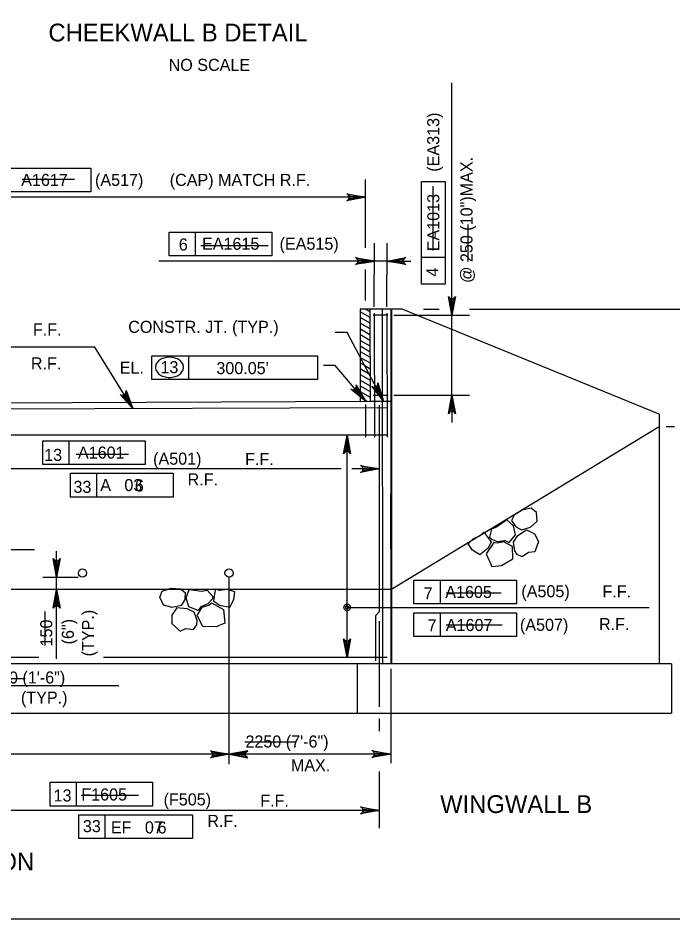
# Model space of a CAD drawing. Extents: x 179 to 454, y -271 to 54.
# Drawn here: x 258.44 to 264.96, y -43.25 to -34.28 of the extents above; entities that cross this region are included whole.
import ezdxf

# ---------------------------------------------------------------- set-up
doc = ezdxf.new("R2010")
doc.units = 0
for name, color, linetype in [('Level 1', 7, 'Continuous'), ('Level 10', 7, 'Continuous'), ('Level 3', 7, 'Continuous'), ('Level 4', 7, 'Continuous'), ('Level 41', 7, 'Continuous'), ('Level 5', 7, 'Continuous')]:
    doc.layers.add(name, color=color, linetype=linetype)

# ---------------------------------------------------------------- blocks, each defined once
blk = doc.blocks.new('ROCK')
at = {"layer": 'Level 4'}
for points in [[(1.578, 0.725), (1.471, 0.551), (1.586, 0.338), (1.78, 0.206), (2.086, 0.269), (2.323, 0.452), (2.328, 0.749), (2.171, 0.911), (1.856, 0.872)], [(0.734, -0.018), (0.934, -0.106), (1.192, -0.099), (1.321, -0.177), (1.562, 0.063), (1.519, 0.367), (1.313, 0.589), (0.948, 0.369), (0.769, 0.319), (0.674, 0.055)], [(0.498, 0.24), (0.588, 0.107), (0.715, -0.096), (0.595, -0.305), (0.299, -0.506), (0.067, -0.329), (-0.063, -0.098), (0.135, 0.068), (0.386, 0.147)], [(1.488, -0.478), (1.468, -0.178), (1.636, 0.025), (1.939, 0.193), (2.2, 0.032), (2.312, -0.229), (2.154, -0.57), (1.947, -0.574), (1.718, -0.703), (1.56, -0.603)], [(0.806, -0.129), (0.519, -0.492), (0.672, -0.928), (0.991, -0.931), (1.399, -0.738), (1.422, -0.324), (1.149, -0.136), (0.916, -0.16)]]:
    blk.add_lwpolyline(points, close=True, dxfattribs=at)

msp = doc.modelspace()

# ---------------------------------------------------------------- linework, layer by layer
at = {"layer": 'Level 1'}
msp.add_lwpolyline([(245.497, -43.25), (276.997, -43.25), (276.997, -22.75), (245.497, -22.75)], close=True, dxfattribs=at)
at = {"layer": 'Level 10'}
for p, q in [((261.8423, -37.2006), (261.9415, -37.2578)), ((261.8442, -37.177), (261.8467, -38.0953)), ((262.1497, -37.177), (261.8442, -37.177)), ((261.8998, -37.177), (261.9412, -37.2009)), ((261.9431, -37.177), (261.9457, -38.0948)), ((262.0661, -37.177), (262.0687, -40.708)), ((262.1497, -37.177), (262.1497, -40.708)), ((262.1587, -37.177), (262.1587, -40.708)), ((262.2652, -37.177), (262.1587, -37.177)), ((264.8223, -38.2227), (262.2652, -37.177)), ((261.8426, -37.2576), (261.9418, -37.3148)), ((261.8428, -37.3146), (261.9421, -37.3718)), ((261.8432, -37.3716), (261.9423, -37.4288)), ((261.8434, -37.4286), (261.9426, -37.4858)), ((261.8438, -37.4856), (261.9429, -37.5428)), ((261.844, -37.5426), (261.9432, -37.5998)), ((261.8443, -37.5995), (261.9435, -37.6568)), ((261.8446, -37.6565), (261.8471, -37.6579)), ((261.8471, -37.6579), (261.9437, -37.7138)), ((261.8448, -37.7135), (261.8907, -37.74)), ((261.8907, -37.74), (261.9441, -37.7707)), ((261.8452, -37.7705), (261.9345, -37.8221)), ((261.8454, -37.8275), (261.9446, -37.8847)), ((261.9345, -37.8221), (261.9443, -37.8278)), ((261.8458, -37.8845), (261.9449, -37.9417)), ((261.846, -37.9415), (261.9452, -37.9988)), ((261.8463, -37.9985), (261.9455, -38.0557)), ((253.2639, -38.1317), (261.9457, -38.0948)), ((261.8466, -38.0555), (261.915, -38.0949)), ((261.9457, -38.0948), (262.1543, -38.0939)), ((264.8223, -38.2227), (264.8223, -40.708)), ((262.1497, -39.9698), (264.8223, -38.3458)), ((262.0111, -39.9698), (253.6367, -39.9698)), ((262.1543, -39.9698), (262.0111, -39.9698)), ((259.0207, -40.708), (256.7722, -40.708)), ((264.9454, -40.708), (259.0207, -40.708)), ((261.815, -40.708), (261.815, -41.2001)), ((264.9454, -40.708), (264.9454, -41.2001)), ((249.6966, -41.2001), (264.9454, -41.2001))]:
    msp.add_line(p, q, dxfattribs=at)
at = {"layer": 'Level 3'}
for p, q in [((262.7585, -37.2385), (262.7585, -34.9256)), ((258.1427, -35.774), (259.1642, -35.774)), ((259.1642, -35.774), (259.1642, -36.0102)), ((261.8995, -36.5671), (261.8995, -35.887)), ((262.4572, -36.9288), (262.4572, -35.9073)), ((262.4572, -35.9073), (262.6934, -35.9073)), ((262.6934, -35.9073), (262.6934, -36.9288)), ((259.1642, -36.0102), (258.1427, -36.0102)), ((261.8995, -36.0642), (257.699, -36.0642)), ((259.9434, -36.4099), (260.9649, -36.4099)), ((259.9434, -36.6461), (259.9434, -36.4099)), ((260.2072, -36.6461), (260.2072, -36.4099)), ((260.9649, -36.4099), (260.9649, -36.6461)), ((261.9841, -37.1565), (261.9867, -36.5225)), ((262.1107, -37.1565), (262.1133, -36.5225)), ((260.9649, -36.6461), (259.9434, -36.6461)), ((262.6934, -36.6652), (262.4572, -36.6652)), ((261.0277, -36.6997), (259.8401, -36.6997)), ((261.9859, -36.6997), (260.7614, -36.6997)), ((262.1133, -36.6997), (261.9867, -36.6997)), ((262.1126, -36.6997), (262.3496, -36.6997)), ((261.8995, -37.0904), (261.8995, -36.7846)), ((262.6934, -36.9288), (262.4572, -36.9288)), ((262.7585, -37.1204), (262.7585, -37.0023)), ((262.4756, -37.177), (262.633, -37.177)), ((262.9346, -37.177), (268.2215, -37.177)), ((262.1805, -37.2385), (262.9357, -37.2385)), ((262.7585, -38.0704), (262.7585, -37.2385)), ((261.7145, -37.4091), (261.5964, -37.4091)), ((262.0794, -38.0942), (261.7145, -37.4091)), ((259.2046, -37.5568), (256.5932, -37.5568)), ((259.5829, -38.1663), (259.2046, -37.5568)), ((259.7718, -37.6433), (260.1387, -37.6433)), ((259.7718, -37.8795), (259.7718, -37.6433)), ((260.1387, -37.8795), (260.1387, -37.6433)), ((260.1387, -37.6433), (261.4202, -37.6433)), ((261.4202, -37.6433), (261.4202, -37.8795)), ((261.5978, -37.7378), (261.4797, -37.7378)), ((261.8999, -38.095), (261.5978, -37.7378)), ((261.4202, -37.8795), (259.7718, -37.8795)), ((262.1805, -38.0332), (262.9357, -38.0332)), ((262.7585, -38.0704), (262.7585, -38.3066)), ((261.7154, -39.5806), (261.7154, -38.4319)), ((258.6842, -38.4892), (259.7057, -38.4892)), ((258.6842, -38.7255), (258.6842, -38.4892)), ((258.9479, -38.7255), (258.9479, -38.4892)), ((259.7057, -38.4892), (259.7057, -38.7255)), ((259.7057, -38.7255), (258.6842, -38.7255)), ((261.6557, -38.7692), (257.6659, -38.7692)), ((258.9612, -39.0487), (258.9612, -38.8125)), ((258.9612, -38.8125), (259.9827, -38.8125)), ((259.2249, -39.0487), (259.2249, -38.8125)), ((259.9827, -38.8125), (259.9827, -39.0487)), ((262.0361, -38.7692), (261.7622, -38.7692)), ((262.1497, -39.5671), (262.1497, -39.0198)), ((259.9827, -39.0487), (258.9612, -39.0487)), ((261.7154, -40.6465), (261.7154, -39.5068)), ((257.9022, -39.5727), (258.6038, -39.5727)), ((258.8218, -40.6597), (258.8218, -39.5877)), ((258.6867, -39.8468), (259.0362, -39.8468)), ((262.3814, -39.8768), (263.4029, -39.8768)), ((262.3814, -40.1131), (262.3814, -39.8768)), ((262.6451, -40.1131), (262.6451, -39.8768)), ((263.4029, -39.8768), (263.4029, -40.1131)), ((261.7154, -40.1481), (264.7239, -40.1481)), ((263.4029, -40.1131), (262.3814, -40.1131)), ((262.3814, -40.4363), (262.3814, -40.2001)), ((262.3814, -40.2001), (263.4029, -40.2001)), ((262.6451, -40.4363), (262.6451, -40.2001)), ((263.4029, -40.2001), (263.4029, -40.4363)), ((263.4029, -40.4363), (262.3814, -40.4363)), ((262.1498, -40.7605), (262.1498, -41.6998)), ((259.4417, -40.9298), (257.6044, -40.9298)), ((262.0361, -41.2551), (262.0361, -41.3808)), ((262.1498, -41.6097), (250.9023, -41.6097)), ((262.0361, -41.7823), (262.0361, -42.3463)), ((258.7577, -42.1254), (258.7577, -41.8892)), ((258.7577, -41.8892), (259.7792, -41.8892)), ((259.0213, -42.1254), (259.0213, -41.8892)), ((259.7792, -41.8892), (259.7792, -42.1254)), ((259.7792, -42.1254), (258.7577, -42.1254)), ((262.0361, -42.1691), (257.6659, -42.1691)), ((259.0438, -42.2124), (260.175, -42.2124)), ((259.0438, -42.4486), (259.0438, -42.2124)), ((259.3075, -42.4486), (259.3075, -42.2124)), ((260.175, -42.2124), (260.175, -42.4486)), ((260.175, -42.4486), (259.0438, -42.4486))]:
    msp.add_line(p, q, dxfattribs=at)
for points in [[(261.8995, -36.0642), (261.7131, -36.0991), (261.7274, -36.0892), (261.7348, -36.0767), (261.737, -36.0642), (261.7348, -36.0517), (261.7274, -36.0392), (261.7131, -36.0292), (261.8995, -36.0642), (261.7274, -36.0392), (261.7348, -36.0517), (261.8995, -36.0642), (261.737, -36.0642), (261.7348, -36.0767), (261.8995, -36.0642), (261.7274, -36.0892)], [(261.9859, -36.6997), (261.7995, -36.7346), (261.8138, -36.7247), (261.8212, -36.7122), (261.8234, -36.6997), (261.8212, -36.6872), (261.8138, -36.6747), (261.7995, -36.6647), (261.9859, -36.6997), (261.8138, -36.6747), (261.8212, -36.6872), (261.9859, -36.6997), (261.8234, -36.6997), (261.8212, -36.7122), (261.9859, -36.6997), (261.8138, -36.7247)], [(262.1126, -36.6997), (262.299, -36.6647), (262.2847, -36.6747), (262.2772, -36.6872), (262.2751, -36.6997), (262.2772, -36.7122), (262.2847, -36.7247), (262.299, -36.7346), (262.1126, -36.6997), (262.2847, -36.7247), (262.2772, -36.7122), (262.1126, -36.6997), (262.2751, -36.6997), (262.2772, -36.6872), (262.1126, -36.6997), (262.2847, -36.6747)], [(262.7585, -37.2385), (262.7236, -37.0521), (262.7335, -37.0664), (262.746, -37.0738), (262.7585, -37.076), (262.771, -37.0738), (262.7835, -37.0664), (262.7934, -37.0521), (262.7585, -37.2385), (262.7835, -37.0664), (262.771, -37.0738), (262.7585, -37.2385), (262.7585, -37.076), (262.746, -37.0738), (262.7585, -37.2385), (262.7335, -37.0664)], [(261.8999, -38.095), (261.7528, -37.9752), (261.7697, -37.9797), (261.7841, -37.9773), (261.795, -37.9709), (261.8032, -37.9612), (261.8079, -37.9475), (261.8062, -37.9301), (261.8999, -38.095), (261.8079, -37.9475), (261.8032, -37.9612), (261.8999, -38.095), (261.795, -37.9709), (261.7841, -37.9773), (261.8999, -38.095), (261.7697, -37.9797)], [(262.0794, -38.0942), (261.9609, -37.9462), (261.9765, -37.9542), (261.991, -37.9548), (262.003, -37.9508), (262.0131, -37.9431), (262.0206, -37.9307), (262.0227, -37.9132), (262.0794, -38.0942), (262.0206, -37.9307), (262.0131, -37.9431), (262.0794, -38.0942), (262.003, -37.9508), (261.991, -37.9548), (262.0794, -38.0942), (261.9765, -37.9542)], [(259.5829, -38.1663), (259.4549, -38.0264), (259.4709, -38.0333), (259.4855, -38.033), (259.4973, -38.0282), (259.5068, -38.0198), (259.5134, -38.007), (259.5143, -37.9895), (259.5829, -38.1663), (259.5134, -38.007), (259.5068, -38.0198), (259.5829, -38.1663), (259.4973, -38.0282), (259.4855, -38.033), (259.5829, -38.1663), (259.4709, -38.0333)], [(262.7585, -38.0332), (262.7934, -38.2196), (262.7835, -38.2052), (262.771, -38.1978), (262.7585, -38.1957), (262.746, -38.1978), (262.7335, -38.2052), (262.7236, -38.2196), (262.7585, -38.0332), (262.7335, -38.2052), (262.746, -38.1978), (262.7585, -38.0332), (262.7585, -38.1957), (262.771, -38.1978), (262.7585, -38.0332), (262.7835, -38.2052)], [(261.7154, -38.4319), (261.7503, -38.6183), (261.7404, -38.604), (261.7279, -38.5966), (261.7154, -38.5944), (261.7029, -38.5966), (261.6904, -38.604), (261.6805, -38.6183), (261.7154, -38.4319), (261.6904, -38.604), (261.7029, -38.5966), (261.7154, -38.4319), (261.7154, -38.5944), (261.7279, -38.5966), (261.7154, -38.4319), (261.7404, -38.604)], [(262.0361, -38.7692), (261.8497, -38.8041), (261.864, -38.7942), (261.8714, -38.7817), (261.8736, -38.7692), (261.8714, -38.7567), (261.864, -38.7442), (261.8497, -38.7342), (262.0361, -38.7692), (261.864, -38.7442), (261.8714, -38.7567), (262.0361, -38.7692), (261.8736, -38.7692), (261.8714, -38.7817), (262.0361, -38.7692), (261.864, -38.7942)], [(258.8218, -39.8466), (258.7869, -39.6602), (258.7968, -39.6745), (258.8093, -39.6819), (258.8218, -39.6841), (258.8343, -39.6819), (258.8468, -39.6745), (258.8567, -39.6602), (258.8218, -39.8466), (258.8468, -39.6745), (258.8343, -39.6819), (258.8218, -39.8466), (258.8218, -39.6841), (258.8093, -39.6819), (258.8218, -39.8466), (258.7968, -39.6745)], [(258.8218, -39.9698), (258.8567, -40.1562), (258.8468, -40.1419), (258.8343, -40.1345), (258.8218, -40.1323), (258.8093, -40.1345), (258.7968, -40.1419), (258.7869, -40.1562), (258.8218, -39.9698), (258.7968, -40.1419), (258.8093, -40.1345), (258.8218, -39.9698), (258.8218, -40.1323), (258.8343, -40.1345), (258.8218, -39.9698), (258.8468, -40.1419)], [(261.7154, -40.6465), (261.6805, -40.4601), (261.6904, -40.4744), (261.7029, -40.4818), (261.7154, -40.484), (261.7279, -40.4818), (261.7404, -40.4744), (261.7503, -40.4601), (261.7154, -40.6465), (261.7404, -40.4744), (261.7279, -40.4818), (261.7154, -40.6465), (261.7154, -40.484), (261.7029, -40.4818), (261.7154, -40.6465), (261.6904, -40.4744)], [(262.0361, -42.1691), (261.8497, -42.204), (261.864, -42.1941), (261.8714, -42.1816), (261.8736, -42.1691), (261.8714, -42.1566), (261.864, -42.1441), (261.8497, -42.1342), (262.0361, -42.1691), (261.864, -42.1441), (261.8714, -42.1566), (262.0361, -42.1691), (261.8736, -42.1691), (261.8714, -42.1816), (262.0361, -42.1691), (261.864, -42.1941)]]:
    msp.add_lwpolyline(points, dxfattribs=at)
for points in [[(261.8686, -36.68), (261.8686, -36.7193), (261.9867, -36.6997)], [(262.2314, -36.68), (262.2314, -36.7193), (262.1133, -36.6997)], [(262.7387, -37.1204), (262.7782, -37.1204), (262.7585, -37.2385)], [(261.8086, -38.0175), (261.8387, -37.9921), (261.8999, -38.095)], [(262.0065, -37.9992), (262.0412, -37.9808), (262.0794, -38.0942)], [(259.5033, -38.0754), (259.5367, -38.0547), (259.5823, -38.1653)], [(261.7351, -38.55), (261.6957, -38.55), (261.7154, -38.4319)], [(258.8416, -40.0879), (258.8022, -40.0879), (258.8218, -39.9698)], [(261.7351, -40.5283), (261.6957, -40.5283), (261.7154, -40.6465)]]:
    msp.add_lwpolyline(points, close=True, dxfattribs=at)
for centre, radius in [((259.0808, -39.8058), 0.041), ((260.5404, -39.8058), 0.041), ((261.7154, -40.1468), 0.0333), ((261.7154, -40.1468), 0.0167)]:
    msp.add_circle(centre, radius, dxfattribs=at)
for centre, radius, start, end in [((259.9332, -37.8051), 0.1465, 106.53583, 125.63164), ((259.9469, -37.8515), 0.1949, 90, 106.53583), ((259.9469, -37.8515), 0.1949, 73.46417, 90), ((259.9607, -37.8051), 0.1465, 54.36836, 73.46417), ((259.8799, -37.7571), 0.0731, 149.97668, 180), ((259.8799, -37.7571), 0.0731, 180, 210.02332), ((259.9121, -37.7757), 0.1103, 125.63164, 149.97668), ((259.9818, -37.7757), 0.1103, 30.02332, 54.36836), ((260.014, -37.7571), 0.0731, 0, 30.02332), ((260.014, -37.7571), 0.0731, 329.97668, 0), ((259.9121, -37.7385), 0.1103, 210.02332, 234.36836), ((259.9332, -37.7091), 0.1465, 234.36836, 253.46417), ((259.9469, -37.6627), 0.1949, 253.46417, 270), ((259.9469, -37.6627), 0.1949, 270, 286.53583), ((259.9607, -37.7091), 0.1465, 286.53583, 305.63164), ((259.9818, -37.7385), 0.1103, 305.63164, 329.97668)]:
    msp.add_arc(centre, radius, start, end, dxfattribs=at)
at = {"layer": 'Level 4'}
msp.add_line((264.8932, -38.3458), (264.9758, -38.3458), dxfattribs=at)
for points in [[(260.5404, -41.6097), (260.354, -41.6446), (260.3683, -41.6347), (260.3757, -41.6222), (260.3779, -41.6097), (260.3757, -41.5972), (260.3683, -41.5847), (260.354, -41.5748), (260.5404, -41.6097), (260.3683, -41.5847), (260.3757, -41.5972), (260.5404, -41.6097), (260.3779, -41.6097), (260.3757, -41.6222), (260.5404, -41.6097), (260.3683, -41.6347)], [(260.5404, -41.6097), (260.7268, -41.6446), (260.7125, -41.6347), (260.7051, -41.6222), (260.7029, -41.6097), (260.7051, -41.5972), (260.7125, -41.5847), (260.7268, -41.5748), (260.5404, -41.6097), (260.7125, -41.5847), (260.7051, -41.5972), (260.5404, -41.6097), (260.7029, -41.6097), (260.7051, -41.6222), (260.5404, -41.6097), (260.7125, -41.6347)], [(262.1497, -41.6083), (261.9633, -41.6433), (261.9777, -41.6333), (261.9851, -41.6208), (261.9873, -41.6083), (261.9851, -41.5958), (261.9777, -41.5833), (261.9633, -41.5734), (262.1497, -41.6083), (261.9777, -41.5833), (261.9851, -41.5958), (262.1497, -41.6083), (261.9873, -41.6083), (261.9851, -41.6208), (262.1497, -41.6083), (261.9777, -41.6333)]]:
    msp.add_lwpolyline(points, dxfattribs=at)
at = {"layer": 'Level 41'}
for p, q in [((258.4805, -35.8838), (259, -35.8838)), ((262.5726, -36.5947), (262.5726, -35.9549)), ((262.9222, -36.7047), (262.9222, -36.3348)), ((260.2587, -36.5436), (260.928, -36.5436)), ((259.0179, -38.6219), (259.5373, -38.6219)), ((262.7011, -40.0013), (263.2505, -40.0013)), ((258.7092, -40.527), (258.7092, -40.1871)), ((262.7011, -40.3212), (263.2605, -40.3212)), ((258.1597, -40.8568), (258.5094, -40.8568)), ((260.6971, -41.4866), (261.2066, -41.4866)), ((259.0688, -42.0164), (259.6382, -42.0164))]:
    msp.add_line(p, q, dxfattribs=at)
at = {"layer": 'Level 5'}
for p, q in [((261.9841, -37.218), (261.9867, -38.4524)), ((262.1107, -37.218), (262.1133, -38.4524)), ((262.121, -37.2385), (261.9738, -37.2385)), ((261.9764, -38.0332), (262.1236, -38.0332)), ((257.6832, -38.1744), (262.1133, -38.1556)), ((261.9002, -38.1269), (261.8995, -38.4524)), ((262.0361, -38.1352), (262.0361, -40.1932)), ((262.1133, -38.4319), (257.6875, -38.4319)), ((260.5404, -41.7069), (260.5404, -39.8468)), ((262.0361, -40.1932), (261.9987, -40.2304)), ((261.9987, -40.2304), (261.9987, -40.6786)), ((262.0361, -40.2861), (262.0361, -41.1386)), ((258.6443, -40.6465), (257.6875, -40.6465)), ((262.1134, -40.6465), (259.2883, -40.6465))]:
    msp.add_line(p, q, dxfattribs=at)

# ---------------------------------------------------------------- block references
at = {"layer": 'Level 3'}
for p, xscale, yscale, rotation in [((262.9356, -39.4839), 0.29527500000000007, 0.29527500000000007, 5.152771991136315), ((260.5676, -39.9722), 0.2952750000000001, -0.29527500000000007, -156.2166383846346)]:
    msp.add_blockref('ROCK', p, dxfattribs=dict(at, xscale=xscale, yscale=yscale, rotation=rotation))

# ---------------------------------------------------------------- texts
for s, height, p in [('CHEEKWALL B DETAIL', 0.177167, (258.7413, -34.5124)), ('NO SCALE', 0.12, (259.938, -34.8057)), ('A1617', 0.12, (258.4701, -35.9509)), ('(A517)', 0.12, (259.205, -35.9509)), ('(CAP) MATCH R.F.', 0.12, (259.9492, -35.9508)), ('EA1615', 0.12, (260.2707, -36.5868)), ('(EA515)', 0.12, (261.043, -36.5868)), ('CONSTR. JT. (TYP.)', 0.12, (259.5359, -37.414)), ('F.F.', 0.12, (258.5872, -37.4405)), ('R.F.', 0.12, (258.5665, -37.7777)), ('EL.', 0.12, (259.451, -37.8203)), ('13', 0.12, (259.8569, -37.8157)), ('A1601', 0.12, (259.0351, -38.6662)), ('(A501)', 0.12, (259.7837, -38.7266)), ('F.F.', 0.12, (260.7002, -38.7308)), ('R.F.', 0.12, (260.127, -38.9333)), ('A   03', 0.12, (259.257, -38.9894)), ('A1605', 0.12, (262.6929, -40.0538)), ('(A505)', 0.12, (263.4507, -40.0467)), ('F.F.', 0.12, (264.2588, -40.048)), ('A1607', 0.12, (262.6988, -40.3829)), ('(A507)', 0.12, (263.4366, -40.3808)), ('R.F.', 0.12, (264.2242, -40.3738)), ('450 (1\'-6")', 0.12, (258.1701, -40.9053)), ('(TYP.)', 0.12, (258.4677, -41.1053)), ('2250 (7\'-6")', 0.12, (260.703, -41.5427)), ('MAX.', 0.12, (261.1555, -41.7794)), ('F1605', 0.12, (259.0687, -42.0703)), ('(F505)', 0.12, (259.8881, -42.1193)), ('F.F.', 0.12, (260.8511, -42.1307)), ('WINGWALL B', 0.17717, (262.6423, -42.195)), ('R.F.', 0.12, (260.3239, -42.3332)), ('EF   07', 0.12, (259.3631, -42.3977)), ('ABUTMENT ELEVATION', 0.177167, (255.9003, -42.7668))]:
    msp.add_text(s, height=height, dxfattribs=at).set_placement(p)
for s, p in [('(EA313)', (262.6332, -35.8093)), ('@ 250 (10")MAX.', (262.9645, -36.9168)), ('EA1013', (262.634, -36.6019)), ('(TYP.)', (259.1945, -40.6351)), ('150', (258.7795, -40.5363)), ('(6")', (258.9945, -40.516))]:
    msp.add_text(s, height=0.12, rotation=90, dxfattribs=at).set_placement(p)
at = {"layer": 'Level 41'}
for s, p in [('6', (260.0395, -36.5939)), ("300.05'", (260.4136, -37.8251)), ('13', (258.6991, -38.6891)), ('33', (258.9906, -39.0073)), ('6', (259.6022, -38.9941)), ('7', (262.4778, -40.0682)), ('7', (262.5175, -40.3865)), ('13', (258.7928, -42.0802)), ('33', (259.0843, -42.3852)), ('6', (259.8284, -42.3984))]:
    msp.add_text(s, height=0.12, dxfattribs=at).set_placement(p)
msp.add_text('4', height=0.12, rotation=90, dxfattribs=at).set_placement((262.6253, -36.8536))

doc.saveas('drawing.dxf')
